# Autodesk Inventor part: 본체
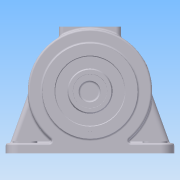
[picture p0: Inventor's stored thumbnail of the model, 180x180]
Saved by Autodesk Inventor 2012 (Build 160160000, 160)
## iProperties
Created: 2015-06
Part Number: 본체
Material: 알루미늄-6061
Document SubType Name: Modeling
Designer: User
Density: 2.71 g/cm^3
Author: User
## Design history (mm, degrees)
sketch "스케치1"
  geometry: C1 r 85 at (0, 0); 2 further points
  constraints: 2 coincident, 1 centre point
  dimensions: "d0" = 170 diameter of C1
extrude "돌출1" new body sketch "스케치1" stored distance "d1" = 118; taper "d2" = 0 deg
sketch "스케치2"
  geometry: C1 r 85 at (0, 0) reference; C2 r 65 at (0, 0)
  constraints: 1 centre point, 1 coincident
  dimensions: "d3" = 130 diameter of C2
extrude "돌출2" join sketch "스케치2" distance "d4" = 13; taper "d5" = 0 deg
sketch "스케치3"
  geometry: C1 r 85 at (0, 0) reference; C2 r 65 at (0, 0)
  constraints: 1 centre point, 1 coincident
  dimensions: "d6" = 130 diameter of C2
extrude "돌출3" join sketch "스케치3" distance "d7" = 3; taper "d8" = 0 deg
sketch "스케치5"
  geometry: L1 (85, -59)-(-85, -59) reference; L2 (-85, 59)-(85, 59) reference; L3 (-74, 51)-(-31, 51); L4 (0, -51)-(-74, -51); L5 (-77, -48)-(-77, 48); L6 (-85, -59)-(-85, 59) reference; L7 (85, -59)-(85, 59) reference; L8 (0, 61.5)-(0, -51); L9 (-31, 51)-(-29.368, 47.5); L10 (-29.368, 47.5)-(-23.5, 47.5); L11 (-23.5, 47.5)-(-23.5, 61.5); L12 (-23.5, 61.5)-(0, 61.5); A1 r 3 centre (-74, 48) between (-74, 51) and (-77, 48); A2 r 3 centre (-74, -48) between (-77, -48) and (-74, -51); 6 further points
  constraints: 16 end point, 6 point on line, 4 point on circle, 4 tangent, 3 perpendicular, 2 centre point, 1 coincident, 1 equal radius, 1 horizontal, 1 horizontal alignment, 1 midpoint, 1 parallel, 1 vertical alignment
  dimensions: "d11" = 8 distance between parallel lines of L2 L3; "d13" = 8 distance between parallel lines of L6 L5; "d100" = 115 deg angle of L3 L9; "d101" = 62 diameter of L3.end L8; "d102" = 3 radius of A1; "d104" = 14 distance between parallel lines of L10 L12; "d105" = 47 diameter of L11 L8; "d106" = 3.5 distance between parallel lines of L10 L3
revolve "회전1" sketch "스케치5" stored, may be unused: angle "d14" = 90 deg
node "작업 평면3"
sketch "스케치6"
  geometry: L1 (-42.5, 42.5)-(42.5, 42.5); L2 (42.5, 42.5)-(42.5, -42.5); L3 (42.5, -42.5)-(-42.5, -42.5); L4 (-42.5, -42.5)-(-42.5, 42.5); 3 further points
  constraints: 8 end point, 2 midpoint, 2 parallel, 1 horizontal, 1 horizontal alignment, 1 perpendicular, 1 vertical alignment
  dimensions: "d28" = 85 distance of L2.end L3.end; "d29" = 85 distance of L3.end L1.start
extrude "돌출4" join sketch "스케치6" stored distance "d17" = 3; taper "d18" = 0 deg
hole "구멍1" diameter "d21" = 95; stored, may be unused: countersink angle "d25" = 90 deg, drill point angle "d27" = 118 deg; dims "d19" = 10, "d20" = 10, "d22" = 6, "d23" = 4, "d24" = 2, "d26" = 50
fillet "모깎기1" dims "d30" = 7
sketch "스케치7"
  geometry: 2 further points
  constraints: 1 coincident
hole "구멍2" sketch "스케치7" at (0, 0) diameter "d31" = 71; stored, may be unused: countersink angle "d35" = 90 deg, drill point angle "d37" = 50 deg; dims "d32" = 6, "d33" = 4, "d34" = 2, "d36" = 50
hole "구멍3" diameter "d40" = 3.242; stored, may be unused: countersink angle "d44" = 90 deg, drill point angle "d46" = 50 deg; dims "d38" = 10, "d39" = 10, "d41" = 10, "d42" = 4, "d43" = 2, "d45" = 13
sketch "스케치8"
  geometry: C1 r 47.5 at (0, 0) reference; 1 further point
  constraints: 1 horizontal alignment
  dimensions: "d53" = 55 distance of C1.centre point (-55, 0)
hole "구멍4" sketch "스케치8" at (-55, 0) diameter "d54" = 3.242; stored, may be unused: countersink angle "d58" = 90 deg, drill point angle "d60" = 50 deg; dims "d55" = 10, "d56" = 4, "d57" = 2, "d59" = 13
node "작업 평면4"
sketch "스케치9"
  geometry: L1 (115, 59)-(-115, 59); L2 (-115, 59)-(-115, -59); L3 (-115, -59)-(115, -59); L4 (115, -59)-(115, 59); 3 further points
  constraints: 8 end point, 2 midpoint, 2 parallel, 1 horizontal, 1 horizontal alignment, 1 perpendicular, 1 vertical alignment
  dimensions: "d65" = 118 distance of L3.end L1.start; "d66" = 230 distance of L1.start L1.end
extrude "돌출5" join sketch "스케치9" distance "d67" = 14; taper "d68" = 0 deg
fillet "모깎기2" dims "d69" = 18
sketch "스케치10"
  geometry: L1 (-32, 81)-(-32, 97); L2 (-50, 81)-(-50, 97); A1 r 18 centre (-41, 97) between (-41, 115) and (-59, 97) reference; A2 r 9 centre (-41, 97) between (-32, 97) and (-50, 97); A3 r 9 centre (-41, 81) between (-50, 81) and (-32, 81); 1 further point
  constraints: 4 end point, 4 point on circle, 4 tangent, 2 centre point, 1 coincident, 1 vertical alignment
  dimensions: "d70" = 18 diameter of A2; "d71" = 18 diameter of A3; "d72" = 16 distance of A1.centre A3.centre
extrude "돌출7" join sketch "스케치10" distance "d78" = 3; taper "d79" = 0 deg
sketch "스케치11"
  geometry: L1 (-50, 81)-(-50, 97) reference; L2 (-32, 97)-(-32, 81) reference; L3 (-45, 97)-(-45, 81); L4 (-37, 81)-(-37, 97); A1 r 9 centre (-41, 81) between (-50, 81) and (-32, 81) reference; A2 r 9 centre (-41, 97) between (-32, 97) and (-50, 97) reference; A3 r 4 centre (-41, 81) between (-45, 81) and (-37, 81); A4 r 4 centre (-41, 97) between (-37, 97) and (-45, 97); 1 further point
  constraints: 4 end point, 4 point on circle, 2 centre point, 3 other
  dimensions: "d80" = 5 distance between parallel lines of L2 L4
extrude "돌출8" cut sketch "스케치11" stored distance "d81" = 3; taper "d82" = 0 deg
sketch "스케치12"
  geometry: L1 (-71, -109)-(-4.703, -84.87); L2 (-71, -115)-(-85, -115) reference; L3 (-71, -97)-(-71, -115) reference; A1 r 85 centre (0, 0) between (-71, -46.733) and (-71, 46.733) reference; 1 further point
  constraints: 2 end point, 1 point on circle, 1 point on line
  dimensions: "d90" = 6 distance from line of L2 L1.start; "d91" = 110 deg angle of L3 L1
feature "리브1" sketch "스케치12" dims "d92" = 1, "d93" = 15, "d94" = 0, "d95" = 0, "d96" = 1, "d97" = 1
fillet "모깎기3" dims "d98" = 7.5
fillet "모깎기4" dims "d99" = 3
hole "구멍5" diameter "d109" = 30; stored, may be unused: countersink angle "d113" = 90 deg, drill point angle "d115" = 0 deg; dims "d107" = 10, "d108" = 10, "d110" = 10, "d111" = 4, "d112" = 2, "d114" = 3
fillet "모깎기5" dims "d116" = 0.3
fillet "모깎기6" dims "d117" = 3
fillet "모깎기9" dims "d120" = 3
fillet "모깎기10" dims "d121" = 3
fillet "모깎기11" dims "d122" = 3
chamfer "모따기1" distance "d123" = 1; stored, may be unused: second distance "d124" = 2, angle "d125" = 45 deg
sketch "스케치13"
  geometry: L1 (0, 0)-(35.923, 77.036); L2 (0, 0)-(85, 0); A1 r 85 centre (0, 0) between (-65.682, -53.953) and (-65.682, 53.953) reference; 1 further point
  constraints: 4 end point, 1 equal length, 1 horizontal, 1 point on circle
  dimensions: "d126" = 65 deg angle of L2 L1
node "작업 평면5"
sketch "스케치14"
  geometry: L1 (-7, -41)-(-7, 41); L2 (-7, 41)-(7, 41); L3 (7, 41)-(7, -41); L4 (7, -41)-(-7, -41); L5 (7, -41)-(-7, 41); L6 (-7, -41)-(-0.002, 0.011); L7 (-0.002, 0.011)-(7, 41); 4 further points
  constraints: 6 end point, 3 midpoint, 1 coincident, 1 horizontal alignment, 1 point on line, 1 vertical alignment, 2 other
  dimensions: "d127" = 82 distance of L2.end L3.end; "d128" = 14 distance of L1.end L2.end
feature "엠보싱1" sketch "스케치14" dims "d0" = 170, "d129" = 0.5, "d130" = 0
node "솔리드1"
pattern_linear "직사각형 패턴1" dims "d49" = 71, "d52" = 71
pattern_circular "원형 패턴1" dims angle "d62" = 360 deg
pattern_linear "직사각형 패턴2" dims "d85" = 178, "d88" = 82
mirror "대칭1"
node "투영된 루프1"
other parameters: "d15" = 88, "d64" = -85
